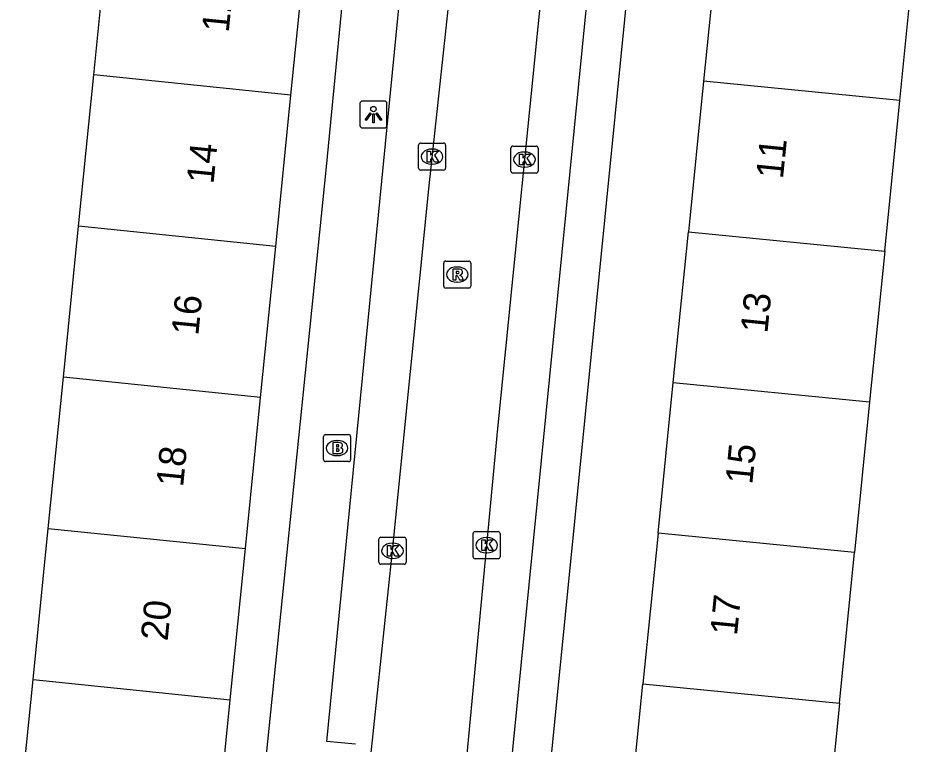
# Model space of a CAD drawing. Extents: x 162250 to 162654, y 380744 to 381605.
# Drawn here: x 162303.76 to 162336.9, y 380840.65 to 380867.49 of the extents above; entities that cross this region are included whole.
import ezdxf

# ---------------------------------------------------------------- set-up
doc = ezdxf.new("R2010")
doc.units = 0
for name, color, linetype in [('IMGEO_Brandkraan', 7, 'Continuous'), ('IMGEO_Kolk', 7, 'Continuous'), ('IMGEO_Lichtpunt', 7, 'Continuous'), ('IMGEO_Pand', 7, 'Continuous'), ('IMGEO_Pand_nummerreeks', 7, 'Continuous'), ('IMGEO_Rijbaan_lokaal_open', 7, 'Continuous'), ('IMGEO_Rioolput', 7, 'Continuous'), ('IMGEO_Voetpad_open', 7, 'Continuous')]:
    doc.layers.add(name, color=color, linetype=linetype)

msp = doc.modelspace()

# ---------------------------------------------------------------- linework, layer by layer
at = {"layer": 'IMGEO_Brandkraan'}
for p, q in [((162315.053, 380851.164), (162315.053, 380852.016)), ((162315.128, 380852.09), (162315.98, 380852.09)), ((162316.054, 380852.016), (162316.054, 380851.164)), ((162315.541, 380851.87), (162315.566, 380851.87)), ((162315.564, 380851.31), (162315.539, 380851.31)), ((162315.98, 380851.09), (162315.128, 380851.09))]:
    msp.add_line(p, q, dxfattribs=at)
for points in [[(162315.053, 380851.164), (162315.053, 380852.016)], [(162315.128, 380852.09), (162315.98, 380852.09)], [(162316.054, 380852.016), (162316.054, 380851.164)], [(162315.401, 380851.79), (162315.401, 380851.39), (162315.614, 380851.39)], [(162315.632, 380851.79), (162315.401, 380851.79)], [(162315.58, 380851.709), (162315.526, 380851.709), (162315.526, 380851.633)], [(162315.526, 380851.633), (162315.579, 380851.633)], [(162315.588, 380851.557), (162315.526, 380851.557), (162315.526, 380851.476)], [(162315.526, 380851.476), (162315.588, 380851.476)], [(162315.98, 380851.09), (162315.128, 380851.09)]]:
    msp.add_lwpolyline(points, dxfattribs=at)
for centre, radius, start, end in [((162315.13, 380852.014), 0.0765, 91.552, 178.448), ((162315.13, 380852.014), 0.0765, 91.552, 178.448), ((162315.978, 380852.014), 0.0765, 1.552, 88.448), ((162315.978, 380852.014), 0.0765, 1.552, 88.448), ((162315.581, 380851.671), 0.0379, 267.8285, 90.9355), ((162315.636, 380851.645), 0.145, 59.4692, 91.5367), ((162315.661, 380851.692), 0.0922, 285.5137, 58.1501), ((162315.666, 380851.5), 0.105, 301.3115, 78.989), ((162315.589, 380851.516), 0.0404, 269.8759, 90.5077), ((162315.62, 380851.641), 0.251, 268.6676, 293.5347), ((162315.13, 380851.166), 0.0765, 181.552, 268.448), ((162315.13, 380851.166), 0.0765, 181.552, 268.448), ((162315.978, 380851.166), 0.0765, 271.552, 358.448), ((162315.978, 380851.166), 0.0765, 271.552, 358.448)]:
    msp.add_arc(centre, radius, start, end, dxfattribs=at)
for centre, major_axis, ratio, start_param, end_param in [((162315.54, 380851.59), (-0.387, 0.002), 0.722429, 4.712389, 7.853982), ((162315.565, 380851.59), (-0.39, 0.002), 0.717154, 1.570796, 4.712389)]:
    msp.add_ellipse(centre, major_axis=major_axis, ratio=ratio, start_param=start_param, end_param=end_param, dxfattribs=at)
at = {"layer": 'IMGEO_Kolk'}
for p, q in [((162318.562, 380861.935), (162318.562, 380862.787)), ((162318.637, 380862.861), (162319.489, 380862.861)), ((162319.05, 380862.641), (162319.075, 380862.641)), ((162319.563, 380862.787), (162319.563, 380861.935)), ((162321.974, 380861.826), (162321.974, 380862.678)), ((162322.049, 380862.752), (162322.901, 380862.752)), ((162322.975, 380862.678), (162322.975, 380861.826)), ((162322.462, 380862.532), (162322.487, 380862.532)), ((162319.073, 380862.081), (162319.048, 380862.081)), ((162322.485, 380861.972), (162322.46, 380861.972)), ((162319.489, 380861.861), (162318.637, 380861.861)), ((162322.901, 380861.752), (162322.049, 380861.752)), ((162317.174, 380848.294), (162318.026, 380848.294)), ((162320.575, 380847.575), (162320.575, 380848.427)), ((162320.65, 380848.501), (162321.502, 380848.501)), ((162321.576, 380848.427), (162321.576, 380847.575)), ((162317.099, 380847.368), (162317.099, 380848.22)), ((162317.587, 380848.074), (162317.612, 380848.074)), ((162318.1, 380848.22), (162318.1, 380847.368)), ((162321.063, 380848.281), (162321.088, 380848.281)), ((162321.086, 380847.721), (162321.061, 380847.721)), ((162318.026, 380847.294), (162317.174, 380847.294)), ((162317.61, 380847.514), (162317.585, 380847.514)), ((162321.502, 380847.501), (162320.65, 380847.501))]:
    msp.add_line(p, q, dxfattribs=at)
for points in [[(162318.562, 380861.935), (162318.562, 380862.787)], [(162318.637, 380862.861), (162319.489, 380862.861)], [(162318.883, 380862.561), (162319.006, 380862.561), (162319.006, 380862.41), (162319.136, 380862.561), (162319.3, 380862.561), (162319.154, 380862.41), (162319.307, 380862.161), (162319.155, 380862.161), (162319.07, 380862.325), (162319.006, 380862.258), (162319.006, 380862.161), (162318.883, 380862.161), (162318.883, 380862.561)], [(162319.563, 380862.787), (162319.563, 380861.935)], [(162321.974, 380861.826), (162321.974, 380862.678)], [(162322.049, 380862.752), (162322.901, 380862.752)], [(162322.975, 380862.678), (162322.975, 380861.826)], [(162322.295, 380862.452), (162322.418, 380862.452), (162322.418, 380862.301), (162322.548, 380862.452), (162322.712, 380862.452), (162322.566, 380862.301), (162322.719, 380862.052), (162322.567, 380862.052), (162322.482, 380862.216), (162322.418, 380862.149), (162322.418, 380862.052), (162322.295, 380862.052), (162322.295, 380862.452)], [(162319.489, 380861.861), (162318.637, 380861.861)], [(162322.901, 380861.752), (162322.049, 380861.752)], [(162317.174, 380848.294), (162318.026, 380848.294)], [(162320.575, 380847.575), (162320.575, 380848.427)], [(162320.65, 380848.501), (162321.502, 380848.501)], [(162321.576, 380848.427), (162321.576, 380847.575)], [(162317.099, 380847.368), (162317.099, 380848.22)], [(162317.42, 380847.994), (162317.543, 380847.994), (162317.543, 380847.843), (162317.673, 380847.994), (162317.837, 380847.994), (162317.691, 380847.843), (162317.844, 380847.594), (162317.692, 380847.594), (162317.607, 380847.758), (162317.543, 380847.691), (162317.543, 380847.594), (162317.42, 380847.594), (162317.42, 380847.994)], [(162318.1, 380848.22), (162318.1, 380847.368)], [(162320.896, 380848.201), (162321.019, 380848.201), (162321.019, 380848.05), (162321.149, 380848.201), (162321.313, 380848.201), (162321.167, 380848.05), (162321.32, 380847.801), (162321.168, 380847.801), (162321.083, 380847.965), (162321.019, 380847.898), (162321.019, 380847.801), (162320.896, 380847.801), (162320.896, 380848.201)], [(162318.026, 380847.294), (162317.174, 380847.294)], [(162321.502, 380847.501), (162320.65, 380847.501)]]:
    msp.add_lwpolyline(points, dxfattribs=at)
for centre, start, end in [((162318.639, 380862.785), 91.552, 178.448), ((162318.639, 380862.785), 91.552, 178.448), ((162319.487, 380862.785), 1.552, 88.448), ((162319.487, 380862.785), 1.552, 88.448), ((162322.051, 380862.676), 91.552, 178.448), ((162322.051, 380862.676), 91.552, 178.448), ((162322.899, 380862.676), 1.552, 88.448), ((162322.899, 380862.676), 1.552, 88.448), ((162318.639, 380861.937), 181.552, 268.448), ((162318.639, 380861.937), 181.552, 268.448), ((162319.487, 380861.937), 271.552, 358.448), ((162319.487, 380861.937), 271.552, 358.448), ((162322.051, 380861.828), 181.552, 268.448), ((162322.051, 380861.828), 181.552, 268.448), ((162322.899, 380861.828), 271.552, 358.448), ((162322.899, 380861.828), 271.552, 358.448), ((162317.176, 380848.218), 91.552, 178.448), ((162317.176, 380848.218), 91.552, 178.448), ((162318.024, 380848.218), 1.552, 88.448), ((162318.024, 380848.218), 1.552, 88.448), ((162320.652, 380848.425), 91.552, 178.448), ((162320.652, 380848.425), 91.552, 178.448), ((162321.5, 380848.425), 1.552, 88.448), ((162321.5, 380848.425), 1.552, 88.448), ((162317.176, 380847.37), 181.552, 268.448), ((162317.176, 380847.37), 181.552, 268.448), ((162318.024, 380847.37), 271.552, 358.448), ((162318.024, 380847.37), 271.552, 358.448), ((162320.652, 380847.577), 181.552, 268.448), ((162320.652, 380847.577), 181.552, 268.448), ((162321.5, 380847.577), 271.552, 358.448), ((162321.5, 380847.577), 271.552, 358.448)]:
    msp.add_arc(centre, 0.0765, start, end, dxfattribs=at)
for centre, major_axis, ratio, start_param, end_param in [((162319.049, 380862.361), (-0.387, 0.002), 0.722429, 4.712389, 7.853982), ((162319.074, 380862.361), (-0.39, 0.002), 0.717154, 1.570796, 4.712389), ((162322.461, 380862.252), (-0.387, 0.002), 0.722429, 4.712389, 7.853982), ((162322.486, 380862.252), (-0.39, 0.002), 0.717154, 1.570796, 4.712389), ((162317.586, 380847.794), (-0.387, 0.002), 0.722429, 4.712389, 7.853982), ((162317.611, 380847.794), (-0.39, 0.002), 0.717154, 1.570796, 4.712389), ((162321.062, 380848.001), (-0.387, 0.002), 0.722429, 4.712389, 7.853982), ((162321.087, 380848.001), (-0.39, 0.002), 0.717154, 1.570796, 4.712389)]:
    msp.add_ellipse(centre, major_axis=major_axis, ratio=ratio, start_param=start_param, end_param=end_param, dxfattribs=at)
at = {"layer": 'IMGEO_Lichtpunt'}
for p, q in [((162316.397, 380864.321), (162316.397, 380863.514)), ((162316.397, 380864.321), (162316.397, 380863.514)), ((162317.299, 380864.416), (162316.491, 380864.416)), ((162317.299, 380864.416), (162316.491, 380864.416)), ((162317.393, 380863.514), (162317.393, 380864.321)), ((162317.393, 380863.514), (162317.393, 380864.321)), ((162316.491, 380863.42), (162317.299, 380863.42)), ((162316.491, 380863.42), (162317.299, 380863.42))]:
    msp.add_line(p, q, dxfattribs=at)
for points in [[(162316.771, 380863.985), (162316.81, 380863.957), (162316.622, 380863.695), (162316.584, 380863.722), (162316.771, 380863.985)], [(162316.873, 380863.937), (162316.92, 380863.937), (162316.92, 380863.615), (162316.873, 380863.615), (162316.873, 380863.937)], [(162316.983, 380863.957), (162317.021, 380863.984), (162317.208, 380863.722), (162317.169, 380863.694), (162316.983, 380863.957)]]:
    msp.add_lwpolyline(points, dxfattribs=at)
msp.add_circle((162316.896, 380864.119), 0.0994, dxfattribs=at)
for centre, start, end in [((162316.491, 380864.321), 90, 180), ((162316.491, 380864.321), 90, 180), ((162317.299, 380864.321), 0, 90), ((162317.299, 380864.321), 0, 90), ((162316.491, 380863.514), 180, 270), ((162316.491, 380863.514), 180, 270), ((162317.299, 380863.514), 270, 0), ((162317.299, 380863.514), 270, 360)]:
    msp.add_arc(centre, 0.0946, start, end, dxfattribs=at)
at = {"layer": 'IMGEO_Pand'}
for points in [[(162306.565, 380865.378), (162307.122, 380870.936)], [(162329.66, 380870.837), (162329.088, 380865.149)], [(162313.849, 380864.627), (162314.409, 380870.206)], [(162336.334, 380864.429), (162336.901, 380870.115)], [(162306.005, 380859.793), (162306.565, 380865.378)], [(162313.849, 380864.627), (162306.565, 380865.378)], [(162329.088, 380865.149), (162328.529, 380859.582)], [(162336.334, 380864.429), (162329.088, 380865.149)], [(162313.289, 380859.043), (162313.849, 380864.627)], [(162335.779, 380858.861), (162336.334, 380864.429)], [(162305.445, 380854.209), (162306.005, 380859.793)], [(162313.289, 380859.043), (162306.005, 380859.793)], [(162327.969, 380854.016), (162328.529, 380859.582)], [(162328.529, 380859.582), (162335.779, 380858.861)], [(162312.729, 380853.459), (162313.289, 380859.043)], [(162335.779, 380858.861), (162335.224, 380853.294)], [(162304.885, 380848.623), (162305.445, 380854.209)], [(162312.729, 380853.459), (162305.445, 380854.209)], [(162327.409, 380848.449), (162327.969, 380854.016)], [(162327.969, 380854.016), (162335.224, 380853.294)], [(162312.169, 380847.873), (162312.729, 380853.459)], [(162335.224, 380853.294), (162334.668, 380847.727)], [(162304.325, 380843.037), (162304.885, 380848.623)], [(162304.885, 380848.623), (162312.169, 380847.873)], [(162327.409, 380848.449), (162326.85, 380842.882)], [(162334.668, 380847.727), (162327.409, 380848.449)], [(162311.609, 380842.288), (162312.169, 380847.873)], [(162334.113, 380842.159), (162334.668, 380847.727)], [(162303.765, 380837.454), (162304.325, 380843.037)], [(162304.325, 380843.037), (162311.609, 380842.288)], [(162326.29, 380837.315), (162326.85, 380842.882)], [(162326.85, 380842.882), (162334.113, 380842.159)], [(162311.049, 380836.704), (162311.609, 380842.288)], [(162334.113, 380842.159), (162333.558, 380836.592)]]:
    msp.add_lwpolyline(points, dxfattribs=at)
at = {"layer": 'IMGEO_Rijbaan_lokaal_open'}
for points in [[(162316.769, 380839.988), (162317.589, 380847.669), (162318.936, 380861.173), (162319.937, 380870.429)], [(162323.26, 380870.111), (162321.48, 380852.317), (162320.213, 380838.831), (162319.086, 380828.026)]]:
    msp.add_lwpolyline(points, dxfattribs=at)
at = {"layer": 'IMGEO_Rioolput'}
for p, q in [((162319.49, 380857.576), (162319.49, 380858.428)), ((162319.565, 380858.502), (162320.417, 380858.502)), ((162319.978, 380858.282), (162320.003, 380858.282)), ((162320.491, 380858.428), (162320.491, 380857.576)), ((162320.001, 380857.722), (162319.976, 380857.722)), ((162320.417, 380857.502), (162319.565, 380857.502))]:
    msp.add_line(p, q, dxfattribs=at)
for points in [[(162319.49, 380857.576), (162319.49, 380858.428)], [(162319.565, 380858.502), (162320.417, 380858.502)], [(162320.491, 380858.428), (162320.491, 380857.576)], [(162320.079, 380858.2), (162319.827, 380858.202), (162319.827, 380857.802)], [(162319.827, 380857.802), (162319.951, 380857.802), (162319.951, 380857.964), (162319.962, 380857.964)], [(162320.005, 380858.121), (162319.951, 380858.121), (162319.951, 380858.04)], [(162319.951, 380858.04), (162320.003, 380858.04)], [(162320.009, 380857.935), (162320.08, 380857.802), (162320.22, 380857.802), (162320.155, 380857.928)], [(162320.417, 380857.502), (162319.565, 380857.502)]]:
    msp.add_lwpolyline(points, dxfattribs=at)
for centre, radius, start, end in [((162319.567, 380858.426), 0.0765, 91.552, 178.448), ((162319.567, 380858.426), 0.0765, 91.552, 178.448), ((162320.415, 380858.426), 0.0765, 1.552, 88.448), ((162320.415, 380858.426), 0.0765, 1.552, 88.448), ((162319.961, 380857.911), 0.0533, 26.0293, 88.6989), ((162319.987, 380858.229), 0.19, 274.7715, 282.9687), ((162320.011, 380858.025), 0.0964, 77.0061, 93.1865), ((162320.025, 380858.082), 0.0378, 276.6634, 79.6772), ((162320.078, 380858.09), 0.109, 350.3612, 89.416), ((162320.076, 380858.09), 0.112, 277.5842, 350.9817), ((162320.06, 380857.875), 0.108, 29.5134, 73.7905), ((162319.567, 380857.578), 0.0765, 181.552, 268.448), ((162319.567, 380857.578), 0.0765, 181.552, 268.448), ((162320.415, 380857.578), 0.0765, 271.552, 358.448), ((162320.415, 380857.578), 0.0765, 271.552, 358.448)]:
    msp.add_arc(centre, radius, start, end, dxfattribs=at)
for centre, major_axis, ratio, start_param, end_param in [((162319.977, 380858.002), (-0.387, 0.002), 0.722429, 4.712389, 7.853982), ((162320.002, 380858.002), (-0.39, 0.002), 0.717154, 1.570796, 4.712389)]:
    msp.add_ellipse(centre, major_axis=major_axis, ratio=ratio, start_param=start_param, end_param=end_param, dxfattribs=at)
at = {"layer": 'IMGEO_Voetpad_open'}
for points in [[(162318.65, 380898.061), (162315.15, 380861.984), (162309.116, 380802.856), (162307.67, 380803.003)], [(162316.236, 380840.651), (162315.17, 380840.746), (162320.433, 380894.347), (162321.981, 380894.236), (162322.208, 380894.288)], [(162325.864, 380893.781), (162327.336, 380893.62), (162325.189, 380872.449), (162325.066, 380871.015), (162320.821, 380828.279), (162319.819, 380828.412)], [(162321.509, 380803.901), (162319.92, 380804.066), (162319.973, 380805.135), (162326.556, 380871.147)]]:
    msp.add_lwpolyline(points, dxfattribs=at)

# ---------------------------------------------------------------- texts
at = {"layer": 'IMGEO_Pand_nummerreeks'}
for s, rotation, p in [('12', 84.2738, (162311.548, 380866.925)), ('11', 84.2592, (162332.019, 380861.511)), ('14', 84.2738, (162310.986, 380861.327)), ('13', 84.2592, (162331.446, 380855.81)), ('16', 84.2738, (162310.425, 380855.727)), ('18', 84.2738, (162309.863, 380850.129)), ('15', 84.2592, (162330.885, 380850.223)), ('17', 84.2592, (162330.323, 380844.636)), ('20', 84.2738, (162309.292, 380844.439))]:
    msp.add_text(s, height=1, rotation=rotation, dxfattribs=at).set_placement(p)

doc.saveas('drawing.dxf')
